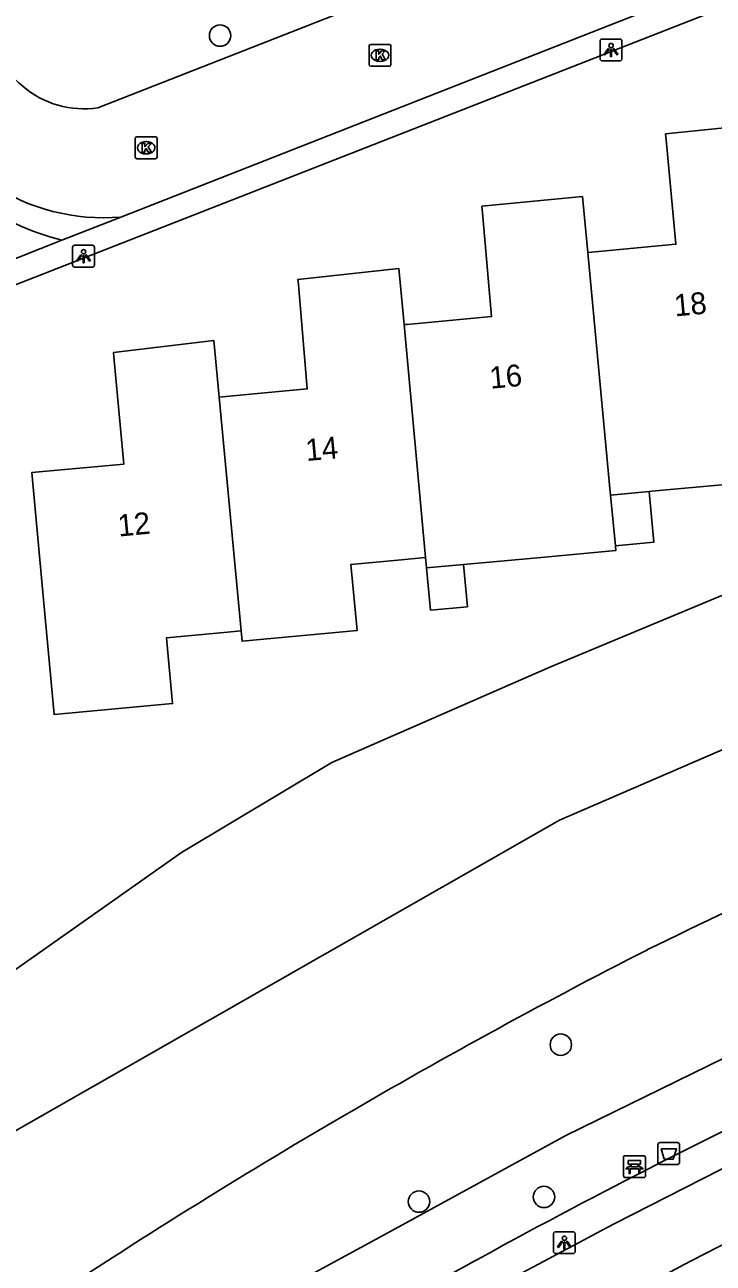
# Model space of a CAD drawing. Extents: x 157793 to 159380, y 380882 to 382313.
# Drawn here: x 158378.3 to 158409.8, y 381119.6 to 381176.2 of the extents above; entities that cross this region are included whole.
import ezdxf

# ---------------------------------------------------------------- set-up
doc = ezdxf.new("R2010")
doc.units = 0
for name, color, linetype in [('IMGEO_Afvalbak', 7, 'Continuous'), ('IMGEO_Bank', 7, 'Continuous'), ('IMGEO_Berm_groen', 7, 'Continuous'), ('IMGEO_Boom', 7, 'Continuous'), ('IMGEO_Damwand', 7, 'Continuous'), ('IMGEO_Erf', 7, 'Continuous'), ('IMGEO_Fietspad_gesloten', 7, 'Continuous'), ('IMGEO_Kolk', 7, 'Continuous'), ('IMGEO_Lichtpunt', 7, 'Continuous'), ('IMGEO_Pand', 7, 'Continuous'), ('IMGEO_Pand_nummerreeks', 7, 'Continuous'), ('IMGEO_Rijbaan_lokaal_open', 7, 'Continuous'), ('IMGEO_Voetpad_open', 7, 'Continuous'), ('IMGEO_Waterloop', 7, 'Continuous')]:
    doc.layers.add(name, color=color, linetype=linetype)

msp = doc.modelspace()

# ---------------------------------------------------------------- linework, layer by layer
at = {"layer": 'IMGEO_Afvalbak'}
for p, q in [((158407.271, 381124.257), (158407.271, 381125.057)), ((158407.271, 381125.057), (158407.271, 381124.257)), ((158407.371, 381125.157), (158408.161, 381125.157)), ((158408.161, 381125.157), (158407.371, 381125.157)), ((158408.261, 381125.057), (158408.261, 381124.257)), ((158408.261, 381124.257), (158408.261, 381125.057)), ((158408.161, 381124.157), (158407.371, 381124.157)), ((158407.371, 381124.157), (158408.161, 381124.157))]:
    msp.add_line(p, q, dxfattribs=at)
msp.add_lwpolyline([(158407.414, 381124.871), (158408.118, 381124.871), (158407.969, 381124.401), (158407.563, 381124.401), (158407.414, 381124.871)], dxfattribs=at)
for centre, start, end in [((158407.371, 381125.057), 90, 180), ((158407.371, 381125.057), 90, 180), ((158408.161, 381125.057), 0, 90), ((158408.161, 381125.057), 360, 90), ((158407.371, 381124.257), 180, 270), ((158407.371, 381124.257), 180, 270), ((158408.161, 381124.257), 270, 0), ((158408.161, 381124.257), 270, 0)]:
    msp.add_arc(centre, 0.1, start, end, dxfattribs=at)
at = {"layer": 'IMGEO_Bank'}
for p, q in [((158405.701, 381123.632), (158405.701, 381124.473)), ((158405.701, 381124.473), (158405.701, 381123.632)), ((158405.776, 381124.557), (158406.617, 381124.557)), ((158406.617, 381124.557), (158405.776, 381124.557)), ((158406.01, 381124.063), (158406.01, 381124.169)), ((158406.054, 381124.169), (158406.054, 381124.063)), ((158406.342, 381124.175), (158406.06, 381124.175)), ((158406.348, 381124.063), (158406.348, 381124.169)), ((158406.392, 381124.169), (158406.392, 381124.063)), ((158406.701, 381124.482), (158406.701, 381123.641)), ((158406.701, 381123.641), (158406.701, 381124.482)), ((158406.626, 381123.557), (158405.785, 381123.557)), ((158405.785, 381123.557), (158406.626, 381123.557)), ((158406.398, 381123.955), (158406.005, 381123.955)), ((158406.06, 381124.057), (158406.342, 381124.057))]:
    msp.add_line(p, q, dxfattribs=at)
for points in [[(158406.004, 381124.175), (158405.918, 381124.175), (158405.918, 381124.336), (158406.481, 381124.336), (158406.481, 381124.175), (158406.398, 381124.175)], [(158405.948, 381123.955), (158405.806, 381123.955), (158405.918, 381124.057), (158406.004, 381124.057)], [(158405.998, 381123.948), (158405.998, 381123.741), (158405.955, 381123.741), (158405.955, 381123.948)], [(158406.398, 381124.057), (158406.481, 381124.057), (158406.593, 381123.955), (158406.454, 381123.955)], [(158406.448, 381123.948), (158406.448, 381123.741), (158406.404, 381123.741), (158406.404, 381123.948)]]:
    msp.add_lwpolyline(points, dxfattribs=at)
for centre, radius, start, end in [((158405.779, 381124.479), 0.0779, 92.4484, 184.2845), ((158405.779, 381124.479), 0.0779, 92.4484, 184.2845), ((158406.003, 381124.168), 0.00671, 2.8957, 87.1043), ((158406.06, 381124.168), 0.00671, 92.8957, 177.1043), ((158406.342, 381124.168), 0.00671, 2.8957, 87.1043), ((158406.399, 381124.168), 0.00671, 92.8957, 177.1043), ((158406.623, 381124.479), 0.0779, 2.4484, 94.2845), ((158406.623, 381124.479), 0.0779, 2.4484, 94.2845), ((158405.779, 381123.635), 0.0779, 182.4484, 274.2845), ((158405.779, 381123.635), 0.0779, 182.4484, 274.2845), ((158405.948, 381123.948), 0.00671, 2.8957, 87.1043), ((158406.005, 381123.948), 0.00671, 92.8957, 177.1043), ((158406.003, 381124.064), 0.00671, 272.8957, 357.1043), ((158406.06, 381124.064), 0.00671, 182.8957, 267.1043), ((158406.342, 381124.064), 0.00671, 272.8957, 357.1043), ((158406.399, 381124.064), 0.00671, 182.8957, 267.1043), ((158406.397, 381123.948), 0.00671, 2.8957, 87.1043), ((158406.454, 381123.948), 0.00671, 92.8957, 177.1043), ((158406.623, 381123.635), 0.0779, 272.4484, 4.2845), ((158406.623, 381123.635), 0.0779, 272.4484, 4.2845)]:
    msp.add_arc(centre, radius, start, end, dxfattribs=at)
at = {"layer": 'IMGEO_Berm_groen'}
msp.add_lwpolyline([(158390.889, 381118.837), (158395.088, 381121.127), (158403.067, 381125.478), (158416.785, 381132.204), (158421.335, 381134.294)], dxfattribs=at)
at = {"layer": 'IMGEO_Boom'}
for centre in [(158387.259, 381175.726), (158402.833, 381129.63), (158402.063, 381122.675), (158396.349, 381122.461)]:
    msp.add_circle(centre, 0.489, dxfattribs=at)
at = {"layer": 'IMGEO_Damwand'}
msp.add_lwpolyline([(158461.647, 381160.946), (158439.392, 381154.94), (158431.317, 381152.221), (158402.773, 381139.885), (158376.054, 381124.651), (158357.637, 381111.936)], dxfattribs=at)
for centre, radius, start, end in [((158549.986, 380841.044), 326.052, 110.23401, 116.05085), ((158534.595, 380883.509), 281.183, 117.03356, 123.72874)]:
    msp.add_arc(centre, radius, start, end, dxfattribs=at)
at = {"layer": 'IMGEO_Erf'}
msp.add_lwpolyline([(158448.623, 381164.199), (158442.422, 381162.212), (158437.246, 381160.472), (158431.501, 381158.604), (158424.709, 381156.548), (158420.131, 381154.666), (158415.517, 381152.366), (158411.111, 381150.536), (158402.33, 381146.878), (158394.215, 381143.332), (158392.367, 381142.523), (158385.487, 381138.402), (158377, 381132.447), (158365.791, 381124.148), (158353.938, 381116.139)], dxfattribs=at)
at = {"layer": 'IMGEO_Fietspad_gesloten'}
for centre, radius, start, end in [((158536.355, 380870.037), 283.526, 115.15573, 121.01923), ((158619.044, 380713.706), 457.247, 116.62274, 119.28105)]:
    msp.add_arc(centre, radius, start, end, dxfattribs=at)
at = {"layer": 'IMGEO_Kolk'}
for p, q in [((158394.068, 381174.397), (158394.068, 381175.249)), ((158394.143, 381175.323), (158394.995, 381175.323)), ((158394.556, 381175.103), (158394.581, 381175.103)), ((158395.069, 381175.249), (158395.069, 381174.397)), ((158394.579, 381174.543), (158394.554, 381174.543)), ((158394.995, 381174.323), (158394.143, 381174.323)), ((158383.453, 381171.1), (158384.305, 381171.1)), ((158383.378, 381170.174), (158383.378, 381171.026)), ((158383.866, 381170.88), (158383.891, 381170.88)), ((158384.379, 381171.026), (158384.379, 381170.174)), ((158384.305, 381170.1), (158383.453, 381170.1)), ((158383.889, 381170.32), (158383.864, 381170.32))]:
    msp.add_line(p, q, dxfattribs=at)
for points in [[(158394.068, 381174.397), (158394.068, 381175.249)], [(158394.143, 381175.323), (158394.995, 381175.323)], [(158394.389, 381175.023), (158394.512, 381175.023), (158394.512, 381174.872), (158394.642, 381175.023), (158394.806, 381175.023), (158394.66, 381174.872), (158394.813, 381174.623), (158394.661, 381174.623), (158394.576, 381174.787), (158394.512, 381174.72), (158394.512, 381174.623), (158394.389, 381174.623), (158394.389, 381175.023)], [(158395.069, 381175.249), (158395.069, 381174.397)], [(158394.995, 381174.323), (158394.143, 381174.323)], [(158383.453, 381171.1), (158384.305, 381171.1)], [(158383.378, 381170.174), (158383.378, 381171.026)], [(158383.699, 381170.8), (158383.822, 381170.8), (158383.822, 381170.649), (158383.952, 381170.8), (158384.116, 381170.8), (158383.97, 381170.649), (158384.123, 381170.4), (158383.971, 381170.4), (158383.886, 381170.564), (158383.822, 381170.497), (158383.822, 381170.4), (158383.699, 381170.4), (158383.699, 381170.8)], [(158384.379, 381171.026), (158384.379, 381170.174)], [(158384.305, 381170.1), (158383.453, 381170.1)]]:
    msp.add_lwpolyline(points, dxfattribs=at)
for centre, start, end in [((158394.145, 381175.247), 91.552, 178.448), ((158394.145, 381175.247), 91.552, 178.448), ((158394.993, 381175.247), 1.552, 88.448), ((158394.993, 381175.247), 1.552, 88.448), ((158394.145, 381174.399), 181.552, 268.448), ((158394.145, 381174.399), 181.552, 268.448), ((158394.993, 381174.399), 271.552, 358.448), ((158394.993, 381174.399), 271.552, 358.448), ((158383.455, 381171.024), 91.552, 178.448), ((158383.455, 381171.024), 91.552, 178.448), ((158384.303, 381171.024), 1.552, 88.448), ((158384.303, 381171.024), 1.552, 88.448), ((158383.455, 381170.176), 181.552, 268.448), ((158383.455, 381170.176), 181.552, 268.448), ((158384.303, 381170.176), 271.552, 358.448), ((158384.303, 381170.176), 271.552, 358.448)]:
    msp.add_arc(centre, 0.0765, start, end, dxfattribs=at)
for centre, major_axis, ratio, start_param, end_param in [((158394.555, 381174.823), (-0.387, 0.002), 0.722429, 4.712389, 7.853982), ((158394.58, 381174.823), (-0.39, 0.002), 0.717154, 1.570796, 4.712389), ((158383.865, 381170.6), (-0.387, 0.002), 0.722429, 4.712389, 7.853982), ((158383.89, 381170.6), (-0.39, 0.002), 0.717154, 1.570796, 4.712389)]:
    msp.add_ellipse(centre, major_axis=major_axis, ratio=ratio, start_param=start_param, end_param=end_param, dxfattribs=at)
at = {"layer": 'IMGEO_Lichtpunt'}
for p, q in [((158404.63, 381175.472), (158404.63, 381174.665)), ((158404.63, 381175.472), (158404.63, 381174.665)), ((158405.532, 381175.567), (158404.724, 381175.567)), ((158405.532, 381175.567), (158404.724, 381175.567)), ((158405.626, 381174.665), (158405.626, 381175.472)), ((158405.626, 381174.665), (158405.626, 381175.472)), ((158404.724, 381174.571), (158405.532, 381174.571)), ((158404.724, 381174.571), (158405.532, 381174.571)), ((158380.518, 381166.051), (158380.518, 381165.244)), ((158380.518, 381166.051), (158380.518, 381165.244)), ((158381.42, 381166.146), (158380.612, 381166.146)), ((158381.42, 381166.146), (158380.612, 381166.146)), ((158381.514, 381165.244), (158381.514, 381166.051)), ((158381.514, 381165.244), (158381.514, 381166.051)), ((158380.612, 381165.15), (158381.42, 381165.15)), ((158380.612, 381165.15), (158381.42, 381165.15)), ((158402.496, 381120.99), (158402.496, 381120.183)), ((158402.496, 381120.99), (158402.496, 381120.183)), ((158403.398, 381121.085), (158402.59, 381121.085)), ((158403.398, 381121.085), (158402.59, 381121.085)), ((158403.492, 381120.183), (158403.492, 381120.99)), ((158403.492, 381120.183), (158403.492, 381120.99)), ((158402.59, 381120.089), (158403.398, 381120.089)), ((158402.59, 381120.089), (158403.398, 381120.089))]:
    msp.add_line(p, q, dxfattribs=at)
for points in [[(158405.004, 381175.136), (158405.043, 381175.108), (158404.855, 381174.846), (158404.817, 381174.873), (158405.004, 381175.136)], [(158405.106, 381175.088), (158405.153, 381175.088), (158405.153, 381174.766), (158405.106, 381174.766), (158405.106, 381175.088)], [(158405.216, 381175.108), (158405.254, 381175.135), (158405.441, 381174.873), (158405.402, 381174.845), (158405.216, 381175.108)], [(158380.892, 381165.715), (158380.931, 381165.687), (158380.743, 381165.425), (158380.705, 381165.452), (158380.892, 381165.715)], [(158380.994, 381165.667), (158381.041, 381165.667), (158381.041, 381165.345), (158380.994, 381165.345), (158380.994, 381165.667)], [(158381.104, 381165.687), (158381.142, 381165.714), (158381.329, 381165.452), (158381.29, 381165.424), (158381.104, 381165.687)], [(158402.87, 381120.654), (158402.909, 381120.626), (158402.721, 381120.364), (158402.683, 381120.391), (158402.87, 381120.654)], [(158402.972, 381120.606), (158403.019, 381120.606), (158403.019, 381120.284), (158402.972, 381120.284), (158402.972, 381120.606)], [(158403.082, 381120.626), (158403.12, 381120.653), (158403.307, 381120.391), (158403.268, 381120.363), (158403.082, 381120.626)]]:
    msp.add_lwpolyline(points, dxfattribs=at)
for centre in [(158405.129, 381175.27), (158381.017, 381165.849), (158402.995, 381120.788)]:
    msp.add_circle(centre, 0.0994, dxfattribs=at)
for centre, start, end in [((158404.724, 381175.472), 90, 180), ((158404.724, 381175.472), 90, 180), ((158405.532, 381175.472), 0, 90), ((158405.532, 381175.472), 0, 90), ((158404.724, 381174.665), 180, 270), ((158404.724, 381174.665), 180, 270), ((158405.532, 381174.665), 270, 0), ((158405.532, 381174.665), 270, 360), ((158380.612, 381166.051), 90, 180), ((158380.612, 381166.051), 90, 180), ((158381.42, 381166.051), 0, 90), ((158381.42, 381166.051), 0, 90), ((158380.612, 381165.244), 180, 270), ((158380.612, 381165.244), 180, 270), ((158381.42, 381165.244), 270, 0), ((158381.42, 381165.244), 270, 360), ((158402.59, 381120.99), 90, 180), ((158402.59, 381120.99), 90, 180), ((158403.398, 381120.99), 0, 90), ((158403.398, 381120.99), 0, 90), ((158402.59, 381120.183), 180, 270), ((158402.59, 381120.183), 180, 270), ((158403.398, 381120.183), 270, 0), ((158403.398, 381120.183), 270, 360)]:
    msp.add_arc(centre, 0.0946, start, end, dxfattribs=at)
at = {"layer": 'IMGEO_Pand'}
for points in [[(158404.061, 381165.821), (158404.232, 381165.837), (158404.716, 381165.881), (158408.095, 381166.192), (158407.649, 381170.967), (158407.624, 381171.238), (158412.259, 381171.705), (158412.502, 381169.117)], [(158395.666, 381162.521), (158395.802, 381162.533), (158396.454, 381162.593), (158399.665, 381162.888), (158399.25, 381167.632), (158399.224, 381167.926), (158403.82, 381168.368), (158404.061, 381165.821)], [(158405.111, 381154.735), (158405.066, 381155.21), (158404.061, 381165.821)], [(158387.219, 381159.214), (158387.382, 381159.229), (158388.329, 381159.316), (158391.245, 381159.584), (158390.835, 381164.352), (158390.815, 381164.589), (158395.427, 381165.088), (158395.666, 381162.521)], [(158395.666, 381162.521), (158396.655, 381151.883)], [(158388.216, 381148.536), (158388.057, 381148.521), (158387.59, 381148.478), (158384.811, 381148.219), (158385.089, 381145.212), (158379.672, 381144.708), (158379.108, 381150.782), (158378.645, 381155.76), (158382.861, 381156.155), (158382.4, 381161.057), (158382.382, 381161.248), (158386.978, 381161.789), (158387.219, 381159.214)], [(158388.216, 381148.536), (158387.219, 381159.214)], [(158413.733, 381155.999), (158413.777, 381155.535), (158410.359, 381155.22), (158407.001, 381154.91), (158406.865, 381154.897)], [(158405.111, 381154.735), (158406.865, 381154.897)], [(158405.33, 381152.42), (158405.111, 381154.735)], [(158406.865, 381154.897), (158407.079, 381152.582), (158405.33, 381152.42)], [(158405.33, 381152.42), (158405.35, 381152.205), (158401.94, 381151.89), (158398.383, 381151.561)], [(158396.655, 381151.883), (158396.486, 381151.867), (158395.555, 381151.78), (158393.239, 381151.565), (158393.519, 381148.547), (158388.261, 381148.059), (158388.216, 381148.536)], [(158396.699, 381151.406), (158396.655, 381151.883)], [(158398.383, 381151.561), (158398.56, 381149.637), (158396.878, 381149.482), (158396.699, 381151.406)], [(158396.699, 381151.406), (158398.383, 381151.561)]]:
    msp.add_lwpolyline(points, dxfattribs=at)
at = {"layer": 'IMGEO_Rijbaan_lokaal_open'}
for points in [[(158423.41, 381188.772), (158381.676, 381172.428)], [(158425.292, 381184.147), (158382.725, 381167.434)], [(158382.725, 381167.434), (158380.022, 381166.386)], [(158380.022, 381166.386), (158374.1, 381164.032), (158345.684, 381144.763), (158345.336, 381148.653), (158349.465, 381151.46)]]:
    msp.add_lwpolyline(points, dxfattribs=at)
for centre, radius, start, end in [((158381.035, 381176.717), 4.336, 181.0378, 278.4957), ((158381.945, 381176.813), 9.411, 199.3996, 274.7535), ((158382.78, 381177.68), 11.625, 211.8489, 256.2756)]:
    msp.add_arc(centre, radius, start, end, dxfattribs=at)
at = {"layer": 'IMGEO_Voetpad_open'}
msp.add_lwpolyline([(158467.081, 381197.838), (158461.541, 381197.122), (158445.123, 381195.558), (158445.198, 381194.878), (158441.151, 381194.476), (158437.204, 381187.562), (158373.758, 381162.728), (158343.94, 381142.482), (158343.198, 381150.791)], dxfattribs=at)
for centre, radius, start, end in [((158538.129, 380866.76), 288.772, 115.1988, 118.8681), ((158536.795, 380869.107), 286.072, 118.86107, 120.98864)]:
    msp.add_arc(centre, radius, start, end, dxfattribs=at)
at = {"layer": 'IMGEO_Waterloop'}
msp.add_lwpolyline([(158357.637, 381111.936), (158376.054, 381124.651), (158402.773, 381139.885), (158431.317, 381152.221), (158439.392, 381154.94), (158461.647, 381160.946)], dxfattribs=at)
for centre, radius, start, end in [((158549.986, 380841.044), 326.052, 110.23401, 116.05085), ((158534.595, 380883.509), 281.183, 117.03356, 123.72874)]:
    msp.add_arc(centre, radius, start, end, dxfattribs=at)

# ---------------------------------------------------------------- texts
at = {"layer": 'IMGEO_Pand_nummerreeks'}
for s, rotation, p in [('18', 5.2483, (158408.055, 381162.894)), ('16', 5.2483, (158399.618, 381159.59)), ('14', 5.2483, (158391.208, 381156.287)), ('12', 5.3514, (158382.625, 381152.838))]:
    msp.add_text(s, height=1, rotation=rotation, dxfattribs=at).set_placement(p)

doc.saveas('drawing.dxf')
